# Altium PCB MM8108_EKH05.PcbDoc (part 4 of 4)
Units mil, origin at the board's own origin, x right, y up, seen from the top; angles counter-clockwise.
Board outline 6023.62 x 3425.2 mil, 4 copper layers (Top Layer, Ground Plane, Middle Layer, Bottom Layer), stack 76.15 mil thick; 188 components, 156 nets, 687 pads, 1369 vias.
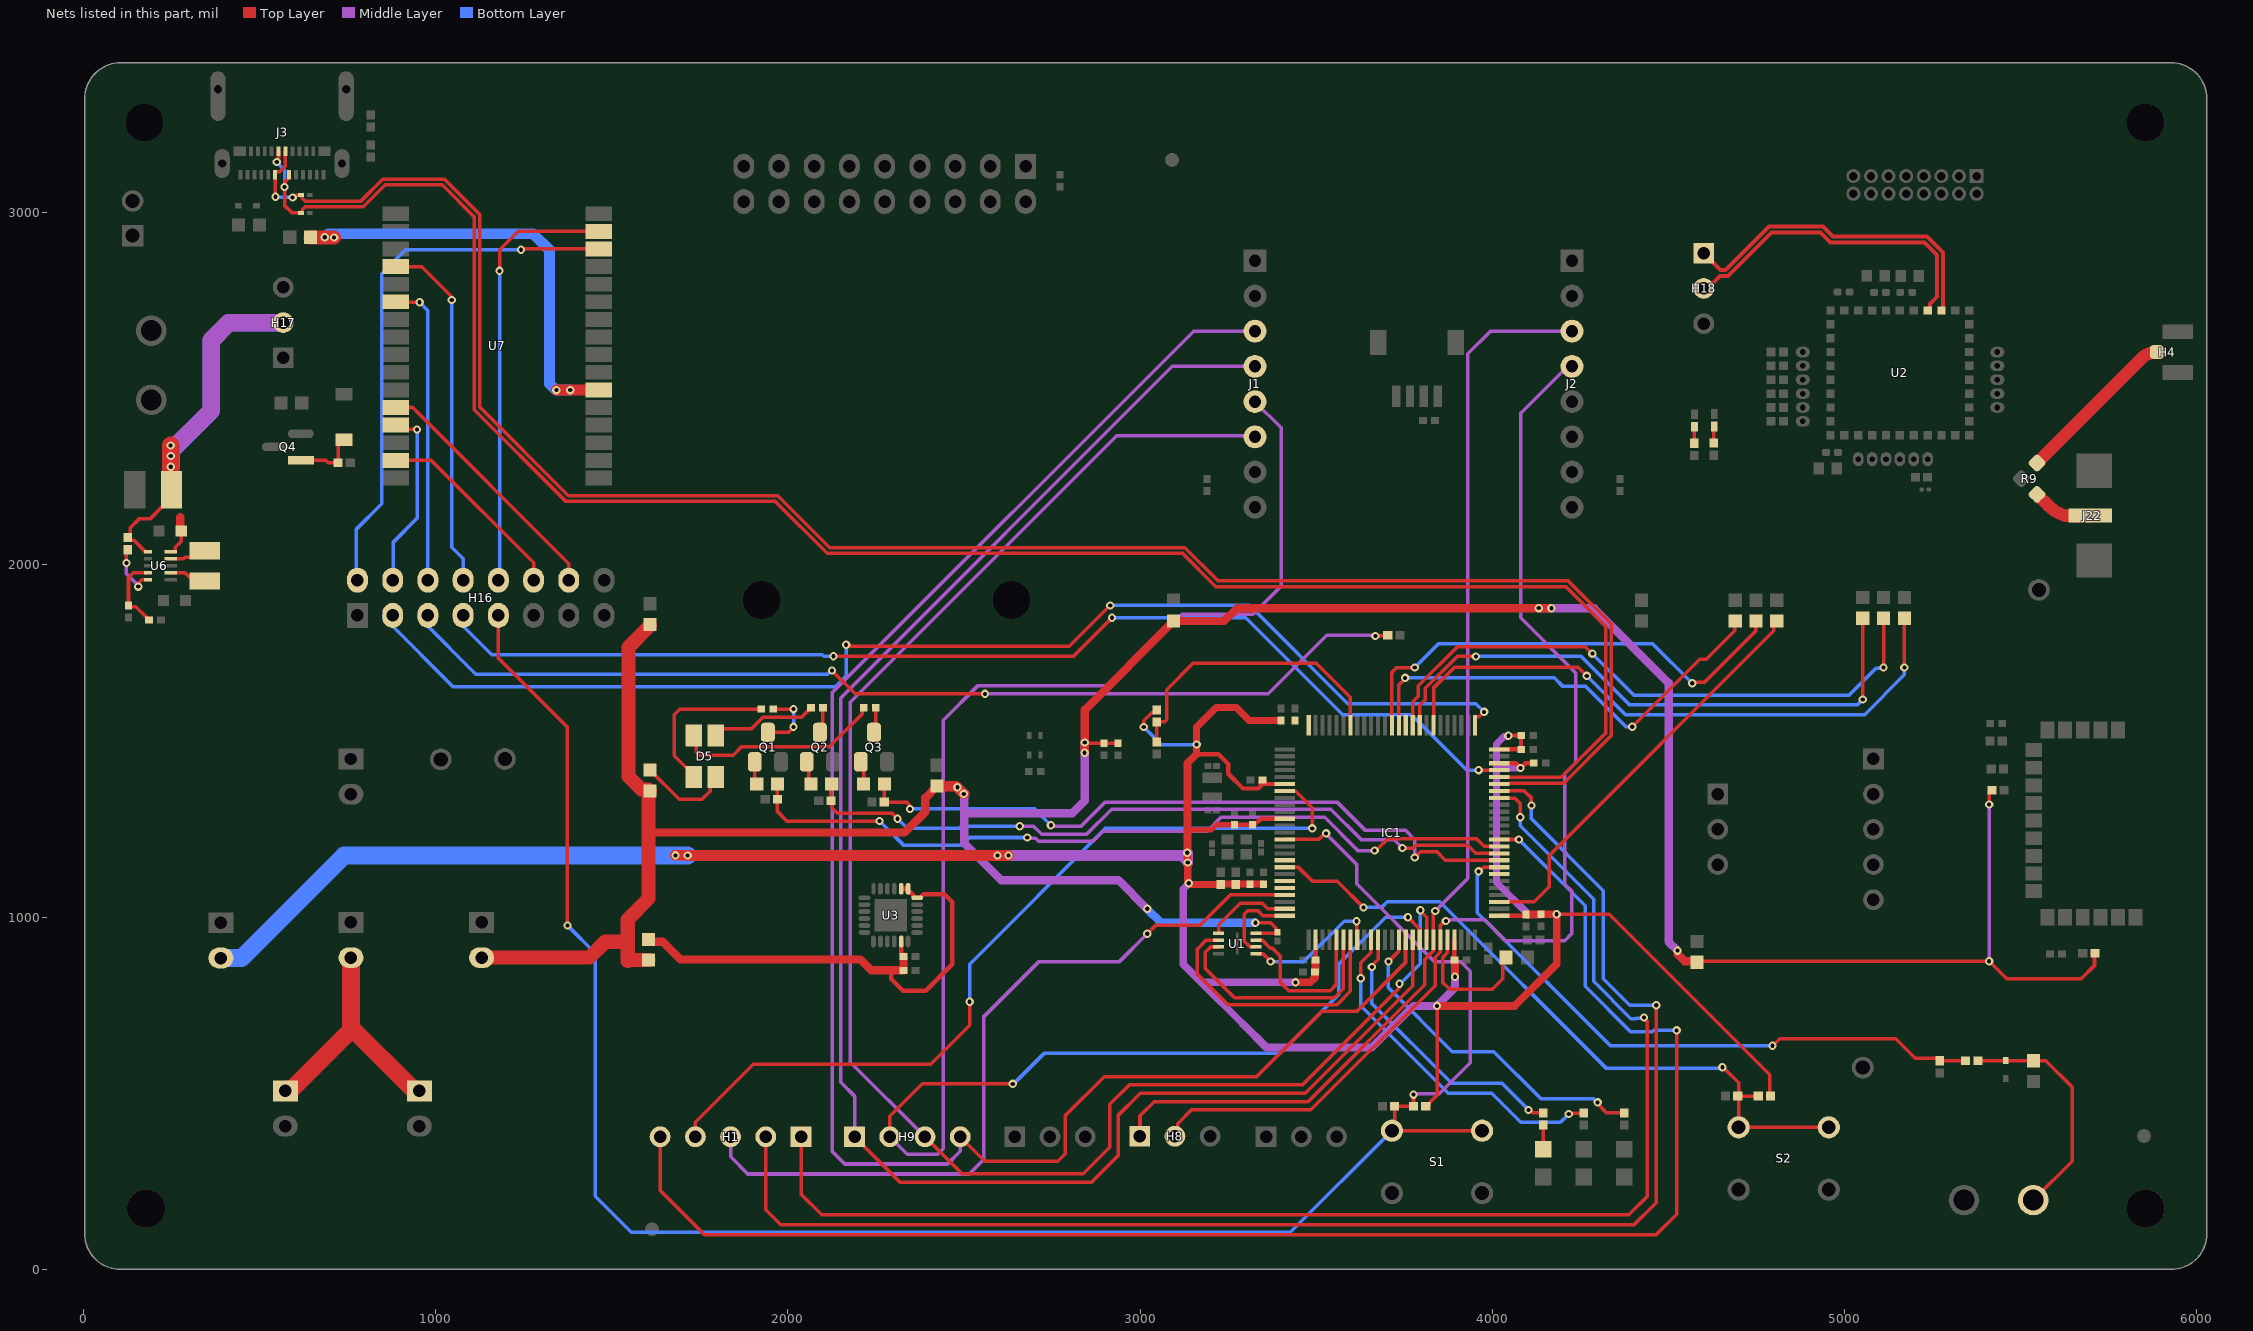
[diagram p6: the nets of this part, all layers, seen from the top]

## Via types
v1: diameter 23.62, hole 11.81, Top Layer to Bottom Layer, tented both sides, 1369 vias

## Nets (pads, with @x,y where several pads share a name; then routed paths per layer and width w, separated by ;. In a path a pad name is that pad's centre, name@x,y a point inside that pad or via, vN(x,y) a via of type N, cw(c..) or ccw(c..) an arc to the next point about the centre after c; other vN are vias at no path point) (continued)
NetD3_A: D3.A R6.2 | length 68.9
  Top Layer w10: D3.A@4143.7,340.94 R6.2@4143.7,409.84
NetD4_K: D4.K H11.2 R51.1 R52.1 | length 665.2
  Top Layer w10: R51.1@5377.95,592.52 D4.K@5456.69,592.52 R52.1@5535.43,592.52 5570.87,592.52 5645.67,517.72 5645.67,307.09 H11.2@5535.43,196.85
NetD5_1: D5.1 R59.1 | length 454.1
  Top Layer w10: D5.1@1732.28,1397.65 1732.28,1405.53 1713.65,1424.15 1711.64,1424.15 1677.17,1458.62 1677.17,1574.8 1692.91,1590.55 R59.1@1923.62,1590.55
NetD5_2: D5.2 R56.2 | length 280.6
  Top Layer w10: R56.2@1621.97,1431.02 R56.2@1608.27,1417.32 1690.94,1334.65 1755.91,1334.65 1778.92,1357.67 1778.92,1381.31 D5.2@1795.27,1397.65
NetD5_3: D5.3 R58.1 | length 303.3
  Top Layer w10: D5.3@1795.27,1515.76 1795.27,1516.81 1813.89,1535.43 1896.96,1535.43 1928.45,1566.93 2037.8,1566.93 R58.1@2065.35,1594.49
NetD5_4: D5.4 R57.1 | length 591.7
  Top Layer w10: D5.4@1732.28,1515.76 1740,1508.04 1740,1470 1750,1460 1844.66,1460 1868.14,1483.48 2117.34,1483.48 2210.71,1576.85 2210.71,1589.91 R57.1@2215.28,1594.49
NetD6_A: D6.A Q4.1 R75.1 | length 184.2
  Top Layer w10: Q4.1@616.82,2297.6 687.4,2297.6 695,2290 R75.1@722.68,2290 722.68,2342.52 735.59,2355.43 D6.A@740,2355.43
NetD7_A: D7.A R17.2 | length 47.7
  Top Layer w10: R17.2@4628.08,2345.89 4628.8,2346.61 4628.8,2392.29 D7.A@4629.53,2393.01
NetD13_A: D13.A R21.2 | length 47.3
  Top Layer w10: R21.2@4572.58,2345.38 4572.75,2345.55 4572.75,2392.32 D13.A@4572.93,2392.5
NetH4_1: H4.1 R9.C | length 467.9
  Top Layer w35.43: R9.C@5545.89,2289.25 5843.39,2586.75 cw(c5885.83,2544.32) H4.1@5885.83,2604.33
NetH16_2: H16.2 U7.30 | length 1548.6
  Top Layer w10: v1(1242.26,2894.52) 1244.59,2896.85 U7.30@1462.76,2896.85
  Bottom Layer w10: H16.2@775,1953.09 775,2101.77 846.46,2173.23 846.46,2826.77 914.21,2894.52 v1(1242.26,2894.52)
NetH16_4: H16.4 U7.13 | length 522.2
  Top Layer w10: U7.13@886.38,2396.85 898.71,2384.52 v1(946.95,2384.52)
  Bottom Layer w10: H16.4@877.76,1956.69 880,1958.94 880,2065 946.95,2131.95 v1(946.95,2384.52)
NetH16_5: H16.5 R3.1 | length 2924.2
  Top Layer w10: v1(2125,1700) 2191.14,1633.86 v1(2559.06,1633.86) ; v1(3667.43,1798.25) 3668.3,1799.13 3701.8,1799.13 R3.1@3702.68,1800
  Middle Layer w10: v1(2559.06,1633.86) 3363.86,1633.86 3530,1800 3665.68,1800 v1(3667.43,1798.25)
  Bottom Layer w10: H16.5@952.76,1856.69 952.76,1850.79 965.26,1838.29 1113.54,1690 2112.33,1690 2122.33,1700 v1(2125,1700)
NetH16_6: H16.6 U7.6 | length 867
  Top Layer w10: U7.6@886.38,2746.85 887.71,2745.51 v1(954.28,2745.51)
  Bottom Layer w10: v1(954.28,2745.51) 977.76,2722.04 H16.6@977.76,1956.69
NetH16_8: H16.8 U7.4 | length 1017.4
  Top Layer w10: U7.4@886.38,2846.85 960.24,2846.85 1047.24,2759.84 v1@1047.24,2748.03
  Bottom Layer w10: v1(1045.28,2751.97) 1045.28,2049.72 1077.76,2017.24 H16.8@1077.76,1956.69
NetH16_10: H16.10 U7.31 | length 1242.1
  Top Layer w10: v1(1181.1,2834.65) 1182.19,2835.73 1182.19,2894.78 1234.25,2946.85 U7.31@1462.76,2946.85
  Bottom Layer w10: H16.10@1177.76,1956.69 1181.1,1960.04 v1(1181.1,2834.65)
NetH16_12: H16.12 U7.15 | length 561
  Top Layer w10: U7.15@886.38,2296.85 986.61,2296.85 1277.76,2005.71 H16.12@1277.76,1956.69
NetH16_14: H16.14 U7.12 | length 721.8
  Top Layer w10: U7.12@886.38,2446.85 934.35,2446.85 1377.76,2003.45 H16.14@1377.76,1956.69
NetIC1_46: IC1.46 L1.2 | length 382.7
  Top Layer w10: IC1.46@3872.05,935.51 3872.05,898.81 3858.27,885.04 3858.27,814.96 3878.23,795 3999.72,795 4029.53,824.8 4029.53,877.36 L1.2@4037.99,885.83
NetJ22_1: J22.1 R9.B | length 172.8
  Top Layer w35.43: R9.B@5545.89,2200.17 5578.07,2167.99 ccw(c5648.78,2238.7) 5609.28,2146.83 5621.46,2141.6 ccw(c5630.83,2163.39) 5629.53,2139.7 5646.84,2138.75 ccw(c5648.78,2174.13) 5648.78,2138.7 J22.1@5697.25,2138.7
NetL3_1: L3.1 U6.9 | length 68.1
  Top Layer w10: U6.9@260.59,2017.05 284.09,2017.05 289.02,2021.97 L3.1@326.61,2021.97
NetL3_2: L3.2 U6.7 | length 84
  Top Layer w10: U6.7@247.87,1977.68 288.23,1977.68 301.02,1964.88 L3.2@326.61,1964.88
NetQ1_D: Q1.D R59.2 | length 187.7
  Top Layer w10: Q1.D@1942.93,1524.37 2000.75,1524.37 2008.94,1532.56 2008.94,1532.81 2015.75,1539.62 v1(2015.75,1540.12) ; R59.2@1958.27,1590.55 v1(2015.75,1590.55)
  Bottom Layer w10: v1(2015.75,1540.12) v1(2015.75,1590.55)
NetQ1_G: Q1.G R62.2 | length 65.4
  Top Layer w10: Q1.G@1905.53,1440.94 1905.53,1383.84 R62.2@1911.42,1377.95
NetQ2_D: Q2.D R58.2 | length 73.7
  Top Layer w10: Q2.D@2090.55,1524.37 2099.21,1533.03 R58.2@2099.21,1594.49
NetQ2_G: Q2.G R63.2 | length 70.5
  Top Layer w10: R63.2@2059.06,1383.86 Q2.G@2059.06,1435.04
  Top Layer w23.62: Q2.G@2053.15,1440.94 Q2.G@2059.06,1435.04 ; R63.2@2059.06,1383.86 R63.2@2064.96,1377.95 ; R63.2@2067.02,1379.83 R63.2@2068.9,1377.95
NetQ3_D: Q3.D R57.2 | length 72.4
  Top Layer w10: Q3.D@2244.11,1524.37 2249.61,1529.87 R57.2@2249.61,1594.49
NetQ3_G: Q3.G R64.2 | length 74.6
  Top Layer w10: Q3.G@2206.71,1440.94 2214.57,1433.09 R64.2@2214.57,1377.95 R64.2@2220.47,1372.05
NetR68_2: R68.2 U6.5 | length 156.7
  Top Layer w10: v1(121.89,2005.24) 121.89,2039.09 R68.2@125.83,2043.03 ; v1(155.35,1938.31) 157.96,1940.91 157.96,1950.65 165.3,1957.99 U6.5@176.1,1957.99
  Middle Layer w10: v1(121.89,2005.24) 121.89,1975.46 154.72,1942.63 v1@154.72,1936.13
NetR71_2: R71.2 R72.1 U6.4 | length 216.3
  Top Layer w10: U6.4@182.91,1977.68 141.57,1977.68 127.79,1963.9 R72.1@127.79,1884.44 130.68,1881.56 148.56,1881.56 179.49,1850.63 180.67,1850.63 186.3,1845 R71.2@186.31,1843.82
NetR73_1: R73.1 U7.22 | length 1325.9
  Top Layer w31: v1(1342.52,2496.06) v1(1381.89,2496.06) 1461.97,2496.06 U7.22@1462.76,2496.85
  Top Layer w40: R73.1@644.53,2930 v1(685,2930) v1@711.44,2930
  Bottom Layer w31: v1@711.44,2940 695,2940 v1(685,2930) 710.71,2930 v1(711.44,2929.28) 722.16,2940 1276.54,2940 1322.83,2893.7 1322.83,2514.22 1340.99,2496.06 v1(1342.52,2496.06) v1(1381.89,2496.06)
PA0: H1.3 IC1.22 | length 2215.6
  Top Layer w10: v1(3019.69,952.76) 3043.31,976.38 3169.29,976.38 3255.91,1062.99 IC1.22@3409.92,1062.99
  Middle Layer w10: H1.3@1837.01,376.69 1837.01,320.09 1886.26,270.84 2514.94,270.84 2555.12,311.02 2555.12,716.54 2712.6,874.02 2940.94,874.02 v1(3019.69,952.76)
PA9: H1.1 IC1.68 | length 3968
  Top Layer w10: H1.1@2037.01,376.69 2037.01,213.61 2095.56,155.06 4387.34,155.06 4440,207.72 4440,702.33 4430,712.33 v1(4430,715) ; IC1.68@4019.21,1338.58 4020.12,1337.68 4063.9,1337.68 4078.74,1322.83 v1@4078.74,1284.32
  Bottom Layer w10: v1(4078.74,1283.46) 4078.74,1259.84 4287.4,1051.18 4287.4,817.6 4392.95,712.05 4408.19,712.05 4408.53,712.39 4427.39,712.39 v1(4430,715)
PA10: H1.2 IC1.69 | length 4217.7
  Top Layer w10: H1.2@1937.01,376.69 1937.01,169.29 1979.38,126.92 4401.92,126.92 4464.54,189.54 4464.54,749.54 v1(4465,750) ; IC1.69@4019.21,1358.27 4090.55,1358.27 4110.63,1338.19 v1(4110.63,1316.83)
  Bottom Layer w10: v1(4110.63,1316.83) 4110.63,1279.13 4314.96,1074.8 4314.96,825.04 4390,750 v1(4465,750)
PC2: IC1.17
PC13: H1.4 IC1.7 | length 2396.4
  Top Layer w10: H1.4@1737.01,376.69 1737.01,418.11 1901.57,582.68 2405.51,582.68 2515.75,692.91 v1(2515.75,759.84) ; IC1.7@3409.92,1358.27 3410.83,1357.36 3441.64,1357.36 3488.19,1310.81 v1(3488.19,1251.97)
  Bottom Layer w10: v1(2515.75,759.84) 2515.75,866.35 2901.37,1251.97 v1(3488.19,1251.97)
PD5: IC1.86
PD10: IC1.57
PD11: C36.1 IC1.58 R51.2 | length 1758.7
  Top Layer w10: v1(3960.63,1129.92) 3963.37,1129.92 3975.18,1141.73 IC1.58@4019.21,1141.73 ; v1(4795,635) 4815,655 5144.62,655 5199.8,599.82 5262.48,599.82 C36.1@5269.69,592.61 ; C36.1@5269.69,592.52 R51.2@5343.31,592.52
  Bottom Layer w10: v1(3960.63,1129.92) 3958.02,1127.31 3958.02,1118.06 3957.21,1117.25 3957.21,1012.79 4335,635 v1(4795,635)
PD15: H1.5 IC1.62 | length 4524.8
  Top Layer w10: H1.5@1637.01,400.68 1637.01,224.1 1762.18,98.92 4465.06,98.92 4522.81,156.67 v1(4522.81,678.54) ; IC1.62@4019.21,1220.47 v1(4074.8,1220.47)
  Bottom Layer w10: v1(4074.8,1220.47) 4262.97,1032.31 4262.97,803.96 4391.93,675 4453.76,675 4457.3,678.54 v1(4522.81,678.54)
PH3-BOOT0: IC1.94 R7.1 R8.1 | length 832.9
  Top Layer w10: R8.1@3047.24,1509.45 R7.1@3047.24,1554.33 ; R7.1@3047.24,1553.54 R7.1@3047.24,1554.33 ; IC1.94@3596.46,1544.8 3596.46,1624.02 3500,1720.47 3149.61,1720.47 3074.8,1645.67 3074.8,1560.19 3068.95,1554.33 R7.1@3047.24,1554.33
SDMMC2_CLK: IC1.87 R31.1 | length 1276.3
  Top Layer w10: IC1.87@3734.25,1544.8 3734.25,1659.18 3751.97,1676.9 v1(3751.97,1679.38) ; v1(4396.65,1540.35) 4527.56,1671.26 4588.58,1732.28 4607.06,1732.28 4687.49,1812.71 4687.49,1839.06 R31.1@4688.98,1840.55
  Bottom Layer w10: v1(3751.97,1679.38) 4175.62,1679.38 4200.12,1654.88 4264.85,1654.88 4379.06,1540.67 4396.33,1540.67 v1(4396.65,1540.35)
SDMMC2_CMD: IC1.88 R32.1 | length 1351.1
  Top Layer w10: IC1.88@3714.57,1544.8 3714.57,1694.88 3728.35,1708.66 v1(3779.53,1708.66) ; v1(4566.93,1664.04) 4569.54,1666.64 4601.97,1666.64 4748.03,1812.71 R32.1@4748.03,1839.06
  Bottom Layer w10: v1(3779.53,1708.66) 3846.46,1775.59 4455.38,1775.59 v1(4566.93,1664.04)
SDMMC2_D0: IC1.53 R33.1 | length 1180.4
  Top Layer w10: IC1.53@4019.21,1043.31 4118.11,1043.31 4161.17,1086.36 4161.17,1174.94 4798.93,1812.71 4798.93,1826.85 4800.21,1828.13 R33.1@4814.35,1828.13
SENSORS_SPI_CLK: H9.1 IC1.41 J1.4 | length 4893.7
  Top Layer w10: H9.1@2188.88,376.69 2317.54,248.03 2862.2,248.03 2937.01,322.83 2937.01,437.01 3000,500 3468.5,500 3773.62,805.12 IC1.41@3773.62,935.51
  Middle Layer w10: H9.1@2188.88,376.69 2188.88,492.22 2149.61,531.5 2149.61,1622.05 3091.14,2563.58 J1.4@3325.59,2563.58
SENSORS_SPI_CS: H9.4 IC1.40 J1.3 | length 5016.4
  Top Layer w10: H9.4@2488.88,376.69 2558.48,307.09 2765.8,307.09 2781.54,322.83 2787.4,328.69 2787.4,437.01 2897.64,547.24 3330.04,547.24 3515.08,732.28 3614.17,732.28 3753.03,871.14 3753.03,934.61 IC1.40@3753.94,935.51
  Middle Layer w10: H9.4@2488.88,376.69 2488.88,335.33 2452.76,299.21 2161.42,299.21 2125.98,334.65 2125.98,1637.8 3151.77,2663.58 J1.3@3325.59,2663.58
SENSORS_SPI_MISO: H9.2 IC1.42 J1.5 | length 4954.8
  Top Layer w10: H9.2@2288.88,376.69 2288.88,434.55 2381.12,526.79 v1(2638.08,526.79) ; v1(3759.7,999.66) 3759.97,999.66 3792.4,967.23 3792.4,936.42 IC1.42@3793.31,935.51
  Middle Layer w10: H9.2@2288.88,376.69 2338.8,326.77 2425.2,326.77 2440.94,342.52 2440.94,1559.06 2539.37,1657.48 2917.32,1657.48 3119.84,1860 3320,1860 3400,1940 3400,2389.17 J1.5@3325.59,2463.58
  Bottom Layer w10: v1@2641.73,527.56 2728.35,614.17 3397.64,614.17 3562.99,779.53 3562.99,866.14 3696.51,999.66 v1(3759.7,999.66)
SENSORS_SPI_MOSI: H9.3 IC1.43 J1.6 | length 4801.9
  Top Layer w10: H9.3@2388.88,376.69 2493.92,271.65 2838.58,271.65 2913.39,346.46 2913.39,468.39 2968.62,523.62 3459.87,523.62 3733.61,797.37 3733.61,808.42 v1(3736.22,811.02) ; v1(3795.28,1019.68) 3795.28,1017.2 3812.99,999.48 IC1.43@3812.99,935.51
  Middle Layer w10: H9.3@2388.88,376.69 2177.17,588.41 2177.17,1610.24 2933.07,2366.14 3323.03,2366.14 J1.6@3325.59,2363.58
  Bottom Layer w10: v1(3736.22,811.02) 3738.41,811.02 3795.28,867.89 v1(3795.28,1019.68)
SENSORS_UART_RX: H8.1 IC1.44 J2.3 | length 3186
  Top Layer w10: H8.1@2998.43,377.95 2999.3,378.83 2999.3,436.31 3039.37,476.38 3476.15,476.38 3807.89,808.12 3807.89,879.92 3831.77,903.79 3831.77,934.61 IC1.44@3832.68,935.51 3831.8,936.39 3831.8,1008.9 3837.51,1014.62 v1(3837.51,1017.31)
  Middle Layer w10: v1(3837.51,1017.31) 3930,1109.79 3930,2599.29 3994.29,2663.58 J2.3@4225.59,2663.58
SENSORS_UART_TX: H8.2 IC1.45 J2.4 | length 3290.3
  Top Layer w10: H8.2@3098.43,377.95 3106.13,385.66 3106.13,413.22 3145.67,452.76 3484.25,452.76 3837,805.5 3837,886.39 3851.46,900.85 3851.46,934.61 IC1.45@3852.36,935.51 3852.36,976.85 3864.51,989 v1(3867.6,989)
  Middle Layer w10: v1(3867.6,989) 3870.2,991.61 3879.75,991.61 3880.27,992.13 3977.87,992.13 4036.93,933.07 4204.72,933.07 4224.41,952.76 4224.41,1074.8 4205.54,1093.68 4205.54,1407.26 4236.22,1437.94 4236.22,1693.3 4080,1849.52 4080,2430.39 4213.19,2563.58 J2.4@4225.59,2563.58 J2.4@4231.69,2563.58
STATUS_LED_B: IC1.36 R6.1 | length 803.6
  Top Layer w10: v1(3657.48,858.27) 3657.48,861.95 3676.1,880.58 3676.1,934.61 IC1.36@3675.2,935.51 ; v1(4102.36,452.76) 4106.05,452.76 4114.32,444.49 R6.1@4143.7,444.49
  Bottom Layer w10: v1(3657.48,858.27) 3657.48,754.79 3884.21,528.06 4027.06,528.06 v1(4102.36,452.76)
STATUS_LED_G: IC1.35 R5.1 | length 980.8
  Top Layer w10: v1(3625.98,826.77) 3625.98,870.08 3654.61,898.7 3654.61,934.61 IC1.35@3655.51,935.51 ; v1(4216.54,440.94) 4218.31,442.72 4257.09,442.72 R5.1@4258.86,444.49
  Bottom Layer w10: v1(3625.98,826.77) 3625.98,748.03 3874.02,500 3997.87,500 4080.55,417.32 4192.91,417.32 v1(4216.54,440.94)
STATUS_LED_R: IC1.39 R4.1 | length 967.7
  Top Layer w10: v1(3704.72,874.02) 3733.35,902.64 3733.35,934.61 IC1.39@3734.25,935.51 ; v1(4298.56,474.16) 4298.56,470.48 4315.31,453.73 4315.31,452.4 4323.23,444.49 R4.1@4374.02,444.49
  Bottom Layer w10: v1(3704.72,874.02) 3704.72,799.21 3885.83,618.11 4003.94,618.11 4137.05,485 4285.9,485 4296.73,474.16 v1(4298.56,474.16)
STM_NRST: C19.1 H16.9 IC1.14 R2.2 S1.1 S1.2 | length 5799
  Top Layer w10: H16.9@1177.76,1865.03 1177.76,1735.63 1374.02,1539.37 v1(1374.02,976.38) ; IC1.14@3409.92,1220.47 3410.83,1221.38 3507.53,1221.38 3523.96,1237.81 v1(3527.65,1237.81) ; v1(3775.59,496.06) 3775.79,495.87 3775.79,462.8 R2.2@3775.98,462.6 C19.1@3722.05,462.6 3722.05,401.18 S1.2@3714.57,393.7 S1.1@3970.47,393.7
  Middle Layer w10: v1(3527.65,1237.81) 3527.65,1236.13 3614.17,1149.61 3614.17,1094.49 3834.65,874.02 3909.45,874.02 3937.01,846.46 3937.01,586.61 3849.06,498.67 3778.2,498.67 v1(3775.59,496.06)
  Bottom Layer w10: v1(1374.02,976.38) 1452.76,897.64 1452.76,207.24 1554.62,105.38 3426.25,105.38 S1.2@3714.57,393.7
STM_QSPI_CLK: IC1.25 U1.6 | length 240.6
  Top Layer w10: U1.6@3328.54,915.35 3312,915.35 3295.28,932.08 3295.28,1007.79 3305.45,1017.97 3334.2,1017.97 3347.98,1004.19 3409.67,1004.19 IC1.25@3409.92,1003.94
STM_QSPI_CS: IC1.24 U1.1 | length 242.8
  Top Layer w10: U1.1@3222.64,954.72 3222.64,978.54 3283.46,1039.37 3346.46,1039.37 3362.2,1023.62 IC1.24@3409.92,1023.62
STM_QSPI_IO0: IC1.33 U1.5 | length 394.5
  Top Layer w10: U1.5@3328.54,895.67 3348.43,895.67 v1(3370.08,874.02) ; v1(3614.17,988.19) 3615.24,987.13 3615.24,936.42 IC1.33@3616.14,935.51
  Bottom Layer w10: v1@3370.94,874.02 3464.57,874.02 3578.74,988.19 v1(3614.17,988.19)
STM_QSPI_IO1: IC1.32 U1.2 | length 775.1
  Top Layer w10: U1.2@3222.64,935.04 3222.56,934.96 3187.22,934.96 3161.42,909.16 3161.42,838.58 3248.03,751.97 3559.06,751.97 3596.46,789.37 IC1.32@3596.46,935.51
STM_QSPI_IO2: IC1.31 U1.3 | length 664.6
  Top Layer w10: 3206.1,915.35 3206.02,915.28 ; U1.3@3222.64,915.35 3222.56,915.28 3206.02,915.28 ; IC1.31@3576.77,935.51 3576.77,797.24 3551.18,771.65 3267.72,771.65 3185.04,854.33 3185.04,900.04 3200.28,915.28 3206.02,915.28
STM_QSPI_IO3: IC1.30 U1.7 | length 465.7
  Top Layer w10: U1.7@3328.54,935.04 3328.62,934.96 3345.94,934.96 3369.07,911.83 3375.57,911.83 3396.88,890.52 3396.88,815.71 3421.26,791.34 3539.37,791.34 3557.09,809.06 IC1.30@3557.09,935.51
STM_SPI2_CLK: IC1.82 R41.2 | length 1729.3
  Top Layer w10: IC1.82@3832.68,1544.8 3832.7,1650.67 3890.94,1708.91 4243.84,1708.91 v1(4267.72,1685.04) ; v1(5169.29,1708.66) R41.2@5169.29,1848.43
  Bottom Layer w10: v1(4267.72,1685.04) 4377.76,1575 5056.31,1575 5169.29,1687.98 v1(5169.29,1708.66)
STM_SPI2_MISO: IC1.84 R43.2 | length 1684.9
  Top Layer w10: IC1.84@3793.31,1544.8 3793.33,1601.38 3809.09,1617.14 3809.09,1649.69 3899.55,1740.16 v1(3952.76,1740.16) ; v1(5051.18,1618.11) R43.2@5051.18,1848.43
  Bottom Layer w10: v1(3952.76,1740.16) 4251.97,1740.16 4389.76,1602.36 5035.43,1602.36 v1(5051.18,1618.11)
STM_SPI2_MOSI: IC1.85 R42.2 | length 1714.5
  Top Layer w10: IC1.85@3773.64,1544.82 3773.64,1611.35 3789.62,1627.32 3789.62,1656.62 3900.71,1767.72 4263.78,1767.72 v1(4283.46,1748.03) ; v1(5110.24,1708.66) R42.2@5110.24,1848.43
  Bottom Layer w10: v1(4283.46,1748.03) 4401.57,1629.92 5012.06,1629.92 5088.2,1706.06 5107.63,1706.06 v1(5110.24,1708.66)
SWD_CLK: H16.3 IC1.76 | length 3541.9
  Top Layer w10: v1(2165,1773.12) 2167.61,1770.52 2176.93,1770.52 2178.88,1768.57 2798.57,1768.57 v1(2915,1885) ; IC1.76@3950.79,1544.8 3950.79,1567.93 3951.69,1568.84 3962.54,1568.84 v1(3976.38,1582.68)
  Bottom Layer w10: H16.3@852.76,1856.69 852.76,1850.79 865.26,1838.29 1049.17,1654.38 2134.38,1654.38 2165,1685 v1(2165,1773.12) ; v1(2915,1885) 3310,1885 3588.7,1606.3 3952.76,1606.3 v1(3976.38,1582.68)
SWD_DIO: H16.7 IC1.72 | length 3234.9
  Top Layer w10: v1(2129.3,1740.7) 2810.7,1740.7 v1(2920,1850) ; v1(3960.63,1417.32) IC1.72@4019.21,1417.32
  Bottom Layer w10: H16.7@1053.94,1849.61 1158.54,1745 2097.49,1745 2101.78,1740.7 v1(2129.3,1740.7) ; v1(2920,1850) 3300,1850 3575.2,1574.8 3770.2,1574.8 3927.68,1417.32 v1(3960.63,1417.32)
TIM4_CH1: IC1.59 R64.1 R67.2 | length 1971.9
  Top Layer w10: R64.1@2273.62,1377.95 2273.23,1377.56 R67.2@2273.23,1326.77 2336.51,1326.77 2343.85,1319.43 2343.85,1309.69 v1(2346.46,1307.09) ; v1(3779.53,1169.29) 3796.48,1186.24 3841.32,1186.24 3866.14,1161.42 IC1.59@4019.21,1161.42
  Middle Layer w10: v1(2746.32,1260.74) 2748.48,1258.59 2832.61,1258.59 2900.79,1326.77 3558.42,1326.77 3637.9,1247.29 3752.4,1247.29 3779.53,1220.16 v1(3779.53,1169.29)
  Bottom Layer w10: v1(2346.46,1307.09) 2699.98,1307.09 v1(2746.32,1260.74)
TIM4_CH2: IC1.60 R63.1 R66.2 | length 2088.7
  Top Layer w10: R63.1@2124.02,1377.95 2122.05,1375.98 R66.2@2122.05,1330.71 2125.64,1327.12 2125.64,1309.36 2139.47,1295.53 2295.02,1295.53 v1(2311.02,1279.53) ; v1(3744.09,1196.19) 3775.19,1196.19 3783,1204 3929.86,1204 3952.76,1181.1 IC1.60@4019.21,1181.1
  Middle Layer w10: v1(2657.88,1258.19) 2696.81,1258.19 2720,1235 2847.59,1235 2918.86,1306.28 3541.01,1306.28 3627.95,1219.34 3721.61,1219.34 3744.09,1196.85 v1(3744.09,1196.19)
  Bottom Layer w10: v1(2311.02,1279.53) 2338.58,1251.97 2485.93,1251.97 2492.16,1258.19 v1(2657.88,1258.19)
TIM4_CH3: IC1.61 R62.1 R65.2 | length 2270
  Top Layer w10: R62.1@1970.47,1377.95 1970.08,1377.56 R65.2@1970.08,1334.65 1970.08,1299.92 1997.28,1272.72 v1(2259.84,1272.72) ; v1(3665.35,1188.98) 3669.04,1188.98 3675.85,1195.79 3676.1,1195.79 3702.31,1222 3955.17,1222 3976.38,1200.79 IC1.61@4019.21,1200.79
  Middle Layer w10: v1(2679.43,1226.13) 2682.03,1223.52 2702.95,1223.52 2711.24,1215.24 2865.88,1215.24 2894.87,1244.23 3189.87,1244.23 3229.11,1283.46 3523.62,1283.46 3618.11,1188.98 v1(3665.35,1188.98)
  Bottom Layer w10: v1(2259.84,1272.72) 2275.84,1256.72 2327.83,1204.72 2494.57,1204.72 2515.98,1226.13 v1(2679.43,1226.13)
USB_D_N: H18.2 U2.27 | length 922.7
  Top Layer w11.13: H18.2@4599.79,2784.94 4611.35,2784.94 4646.11,2819.69 4668.4,2819.69 4792.35,2943.63 4931.59,2943.63 4959.52,2915.71 5226.36,2915.71 5261.71,2880.37 5261.71,2761.22 5241.48,2741 5241.48,2728.69 U2.27@5235.24,2722.44
USB_D_P: H18.1 U2.28 | length 946.9
  Top Layer w11.13: H18.1@4599.79,2884.94 4647.26,2837.47 4661.96,2837.47 4785.25,2960.76 4938.69,2960.76 4966.61,2932.84 5233.46,2932.84 5278.83,2887.47 5278.83,2726.67 U2.28@5274.61,2722.44
USBC_N: D12.K IC1.70 J3.A7 J3.B7 | length 5507.1
  Top Layer w10: J3.A7@544.09,3107.48 544.09,3045.91 v1(545,3045) ; J3.A7@544.49,3116.14 557.11,3116.14 571.21,3130.24 573.23,3132.26 573.23,3174.02 J3.B7@573.62,3174.41 ; v1(593.75,3042.96) 597.37,3042.96 603.63,3049.21 617.01,3049.21 D12.K@617.8,3050 ; D12.K@620.16,3050 620.94,3049.21 620.94,3041.36 629.33,3032.98 787.98,3032.98 850,3095 1025,3095 1125.47,2994.53 1125.47,2447.26 1376.39,2196.34 1970.88,2196.34 2118.09,2049.12 3126.81,2049.12 3221.45,1954.49 4215.51,1954.49 4337.13,1832.87 4337.13,1515.57 4202.18,1380.61 4049.13,1380.61 4047.25,1378.74 4020,1378.74 IC1.70@4019.21,1377.95
  Bottom Layer w10: v1(545,3045) 546.02,3043.98 592.73,3043.98 v1(593.75,3042.96)
USBC_P: D11.K IC1.71 J3.A6 J3.B6 | length 5495.6
  Top Layer w10: J3.A6@583.46,3107.48 583.07,3107.09 583.07,3098.82 573.38,3089.13 573.38,3075.52 v1(570.82,3072.96) 570.82,3020.17 591.77,2999.22 D11.K@617.8,2999.22 ; D11.K@620.95,3000.01 620.95,3007.86 629.83,3016.74 794.7,3016.74 856.73,3078.76 1018.27,3078.76 1109.24,2987.8 1109.24,2440.53 1369.66,2180.1 1964.15,2180.1 2111.37,2032.89 3120.09,2032.89 3214.72,1938.26 4208.78,1938.26 4320.89,1826.14 4320.89,1522.29 4195.45,1396.85 4020,1396.85 IC1.71@4019.21,1397.64
  Top Layer w10.24: v1(548.41,3143.81) 548.41,3147.43 553.54,3152.56 553.54,3174.02 J3.B6@553.94,3174.41
  Bottom Layer w10: v1(548.41,3143.81) 548.41,3142.97 570.82,3120.56 v1(570.82,3072.96)
USER_BUTTON: C20.1 IC1.18 R1.2 S2.1 S2.2 | length 1995.1
  Top Layer w10: IC1.18@3409.92,1141.73 3410.52,1141.14 3449.42,1141.14 3488.88,1101.67 3559.75,1101.67 v1(3633.86,1027.56) ; v1(4652.66,573.92) 4654.43,573.92 4698.82,529.53 C20.1@4698.82,492.13 ; R1.2@4754.33,492.13 C20.1@4698.82,492.13 ; S2.1@4954.72,403.54 S2.2@4698.82,403.54 C20.1@4698.82,492.13
  Bottom Layer w10: v1(3633.86,1027.56) 3685.04,1027.56 3701.13,1043.65 3850.05,1043.65 4322.09,571.61 4650.35,571.61 v1(4652.66,573.92)
VDD_HALOW: H3.1 H19.1 H21.2 | length 724.8
  Top Layer w50: H19.1@572.83,506.69 577.36,511.22 590.73,511.22 763.12,683.62 935.52,511.22 948.88,511.22 H3.1@953.41,506.69 ; 759.39,687.35 H21.2@759.39,885
VDD_MCU: C1.2 C2.2 C3.2 C4.2 C5.2 C6.2 C7.2 C8.2 C9.1 C10.2 C11.2 C14.2 C15.2 C16.2 C17.2 C18.2 C21.2 H24.2 IC1.6 IC1.11 IC1.20 IC1.21 IC1.27 IC1.47 IC1.51 IC1.73 IC1.75 IC1.100 R1.1 R2.1 R7.2 | length 9370.8
  Top Layer w10: v1(3010,1540) 3010,1557.05 3033.14,1580.2 3040.04,1580.2 3047.24,1587.4 R7.2@3047.24,1588.19 ; C18.2@3348.82,1094.49 C18.2@3350.39,1092.91 ; R2.1@3812.62,464.59 3842.52,494.49 v1(3842.52,748.03) ; v1(4045,1515) v1@4045.37,1515.37 ; C10.2@4080.73,1515.37 C10.2@4081.1,1515.75 ; v1(4182.14,1008.07) 4331.93,1008.07 4787.4,552.6 R1.1@4787.4,492.13
  Top Layer w12: 3159.45,1462.6 3222.4,1462.6 3250,1435 3250,1406.98 3291.98,1365 3335,1365 3342,1372 3342,1379 ; C3.2@3267.72,1262.2 C2.2@3318.9,1262.2 ; C2.2@3322.05,1259.06 3342.52,1279.53 IC1.11@3409.92,1279.53 ; IC1.6@3409.92,1377.95 3360.05,1377.95 ; C4.2@3497.31,874.02 3498.03,874.73 IC1.27@3498.03,935.51 ; C9.1@3891.73,878.35 IC1.47@3891.73,935.51 ; IC1.51@4019.21,1003.94 4019.31,1004.03 C6.2@4097.03,1004.03 ; IC1.73@4019.21,1437.01 4066.1,1437.01 v1(4079.67,1423.44) 4093.24,1437.01 C15.2@4116.86,1437.01 ; IC1.75@4019.21,1476.38 4081.1,1476.38 C10.2@4081.1,1515.75 ; v1@4045.37,1515.37 C10.2@4080.73,1515.37 ; 3342,1379 3342,1386 3346,1390 C1.2@3347,1390 3348,1390 3360.05,1377.95 ; 3342,1379 3343.05,1377.95 3360.05,1377.95
  Top Layer w15: 3133.86,1248.03 3202.18,1248.03 3216.35,1262.2 C3.2@3267.72,1262.2
  Top Layer w20: v1(3137.8,1096.12) 3138.78,1096.12 3141.98,1092.91 C17.2@3228.35,1092.91 ; 3159.45,1462.6 3159.45,1539.27 3214.81,1594.63 3272.78,1594.63 3309.41,1558 C14.2@3400,1558 ; C17.2@3232.28,1094.49 C18.2@3348.82,1094.49
  Top Layer w22: v1@3134.47,1155.53 3134.69,1155.75 3133.86,1156.58 3133.86,1248.03 3133.86,1437.01 3159.45,1462.6 ; v1(3135,1155) 3135,1099.35 3137.8,1096.56 v1(3137.8,1096.12) ; v1(3440.94,814.96) 3482.14,814.96 3496.02,828.85 C5.2@3496.02,844.11 3497.31,845.4 C4.2@3497.31,874.02 ; R2.1@3810.63,462.6 3811.42,462.6 3812.62,463.8 R2.1@3812.62,464.59 ; v1@3842.96,748.03 4063.03,748.03 4182.14,867.14 v1(4182.14,1008.07) ; C9.1@3892.45,877.95 3892.45,868.78 3893.7,867.53 v1(3893.7,830.71) ; C6.2@4095.37,1007.6 C7.2@4136.5,1007.6 ; C7.2@4137.08,1008.19 4181.39,1008.19 v1@4181.61,1007.97
  Top Layer w30: v1(1680.47,1175.49) 1714.51,1175.49 v1(1715,1175) v1(2595,1175) 2625.52,1175 v1(2625.78,1175.26)
  Middle Layer w20: v1(3137.8,1096.12) 3137.8,1095.14 3122.05,1079.39 3122.05,866.14 3173.23,814.96 3291.34,696.85 ; v1(4045,1515) 4043.16,1513.16 4033.08,1513.16 4011.81,1491.89 4011.81,1423.44 ; v1(4079.67,1423.44) 4011.81,1423.44 ; v1(4182.14,1008.07) 4101.63,1008.07 4011.81,1097.89 4011.81,1423.44
  Middle Layer w22: 3173.23,814.96 3409.45,814.96 ; 3291.34,696.85 3358.27,629.92 3657.48,629.92 3775.59,748.03 v1(3842.52,748.03) 3893.7,799.21 v1(3893.7,830.71) ; v1@3440.51,814.96 3409.45,814.96 ; v1(3440.94,814.96) 3409.45,814.96
  Middle Layer w30: v1(2595,1175) 3117.43,1175 v1@3135,1157.43 ; v1(3133.59,1182.79) 3135,1181.38 v1@3135,1157.43 ; v1(3135,1155) v1@3135,1157.43
  Bottom Layer w10: v1(3010,1540) 3060,1490 v1(3160,1490)
  Bottom Layer w50: H24.2@390.05,884 448.71,884 739.71,1175 1680.47,1175 v1(1715,1175)
VDD_SENSORS: C24.2 H25.2 R47.1 R48.1 R50.1 R53.1 R54.1 R55.1 R56.1 R61.1 R82.1 R85.1 U1.8 | length 8913
  Top Layer w10: v1@2845.2,1493.38 R85.1@2897.64,1493.38 R82.1@2937.01,1493.38 ; v1(3326.77,984.25) 3370.08,984.25 3386.5,967.83 3386.5,958.07 3389.76,954.8 3328.62,954.8 U1.8@3328.54,954.72 ; R47.1@4583.66,875 v1(5410,875) 5460,825 5671.46,825 5709.05,862.6 R50.1@5709.05,897.24 ; v1(5410,1320) 5410,1352.8 5417.2,1360 R48.1@5417.68,1360
  Top Layer w23.62: R56.1@1604.33,1362.2 R56.1@1608.27,1358.27 ; 1608.27,1240.16 2330.71,1240.16 2389.76,1299.21 2389.76,1338.58 R54.1@2423.23,1372.05 ; v1(2842.23,1466.59) 2842.52,1466.88 v1(2842.52,1496.06) 2842.52,1588.58 R61.1@3094.49,1840.55 3238.19,1840.55 3274.45,1876.81 4131.08,1876.81 v1(4131.46,1877.19) 4166.67,1877.19 v1(4167.08,1876.77) ; v1(4525,905) 4525,895 4545,875 4577.76,875 R47.1@4580.71,872.05 R47.1@4583.66,875 ; R50.1@5709.05,897.24 5709.45,897.64 R50.1@5710.24,897.64
  Top Layer w30: R54.1@2423.23,1372.05 v1@2477.95,1372.05 ; v1(2480.74,1368.61) 2480.74,1368.42 v1(2499.09,1350.07)
  Top Layer w40: H25.2@1130.05,885 1202.86,885 1436.18,885 1481.3,930.12 1545,930.12 ; R53.1@1604.33,877.95 1547.95,877.95 1545,875 1545,930.12 ; R56.1@1604.33,1362.2 1584.14,1362.2 1546.84,1399.51 1546.84,1766.09 R55.1@1608.27,1827.52 ; R56.1@1608.27,1358.27 1604.33,1354.33 1604.33,1240.16 1604.33,1053.15 1545,993.82 1545,930.12
  Middle Layer w10: v1(5410,875) v1(5410,1320)
  Middle Layer w23.62: v1@2500,1350 2500,1299.21 ; v1(2842.23,1466.59) 2842.23,1495.77 v1(2842.52,1496.06) ; v1@2842.52,1466.59 2842.52,1330.71 2807.09,1295.28 2503.94,1295.28 2500,1299.21 ; v1(3019.69,1023.62) 2938.31,1105 2605,1105 2500,1210 2500,1299.21 ; v1(4131.46,1877.19) v1@4166.67,1877.19 ; v1(4167.08,1876.77) 4288.58,1876.77 4500,1665.35 4500,930 v1(4525,905)
  Middle Layer w30: v1(2480.74,1368.61) 2499.35,1350 v1@2500,1350
  Bottom Layer w23.62: v1(3019.69,1023.62) 3059.06,984.25 v1(3326.77,984.25)
VDD_SENSORS_ACC: C37.2 C38.2 R53.2 U3.5 U3.12 U3.13 U3.14 | length 1434.1
  Top Layer w12: 2180,880.95 2180.95,880 ; 2293,849 2293,824 2326,791 2391,791 2466.23,866.23 2466.23,1043.23 2444.47,1065 2384.37,1065 2376.79,1057.42 2376.79,1055.82 2375.97,1055 U3.12@2366.61,1055 2357.25,1055 2356.42,1055.82 2356.42,1062.28 2348.3,1070.41 2341.84,1070.41 2341.02,1071.23 U3.13@2341.02,1080.59 U3.14@2321.33,1080.59 ; C37.2@2321.33,896.32 U3.5@2321.33,930.98
  Top Layer w23.62: R53.2@1604.33,937.01 1611.22,930.12 1644.88,930.12 1695,880 2180.95,880 2206,880 2237,849 2293,849 C38.2@2328,849 C37.2@2328,888
VIN: C42.2 C49.1 H17.2 R68.1 U6.1 U6.10 | length 1762.9
  Top Layer w10: R68.1@125.83,2077.68 125.83,2076.89 133.03,2069.69 143.23,2069.69 176.18,2036.73 U6.1@182.91,2036.73 ; R68.1@126.22,2077.28 132.9,2083.97 132.9,2105.67 158.91,2131.68 190.07,2131.68 223.04,2164.64 C49.1@224.34,2164.64 ; U6.10@247.87,2036.73 260.51,2036.73 260.59,2036.81 260.59,2049.72 277.4,2066.54 C42.2@277.4,2095.79 ; C49.1@249.85,2190.16 C49.1@249.85,2212.79
  Top Layer w23.62: C49.1@241.17,2259.26 C49.1@247.92,2252.5 ; 275.05,2135.46 275.05,2098.14 C42.2@277.4,2095.79
  Top Layer w50: v1@247.28,2308.97 247.92,2308.33 v1(247.92,2278.53) 247.92,2252.5 C49.1@247.92,2212.79 ; v1(247.28,2338.82) 247.52,2338.59 v1(247.52,2308.97)
  Middle Layer w50: v1(247.92,2278.53) 247.92,2323.61 362.19,2437.88 362.19,2637.19 412.87,2687.87 H17.2@566.93,2687.87
  Bottom Layer w50: v1(247.92,2278.53) 247.92,2323.21 362.66,2437.95 362.66,2637.66 412.87,2687.87 H17.2@566.93,2687.87
pads on no net: FID1.1 FID2.1 FID3.1 H5.7 H5.15 IC2.1 IC2.2 IC2.3 IC2.4 IC2.6 IC2.9 IC2.10 IC2.14 IC2.18 IC2.20 J3.A2 J3.A3 J3.A8 J3.A10 J3.A11 J3.B2 J3.B3 J3.B8 J3.B10 J3.B11 M1.1 M2.1 M3.1 M4.1 MH1.1 MH2.1 U3.1 U3.2 U3.15 U3.17 U3.18 U3.19 U3.20 U3.21 U3.22 U3.23 U3.24 U7.1 U7.2 U7.3 U7.7 U7.9 U7.10 U7.11 U7.14 U7.16 U7.17 U7.18 U7.19 U7.20 U7.21 U7.23 U7.25 U7.28 U7.32

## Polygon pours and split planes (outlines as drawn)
GND on Top Layer "Top_GND" (solid, remove dead copper, pour order 19): 23.04,3202.63 23.04,3338.85 cw(c123.04,3338.85) 123.04,3438.85 5946.66,3438.85 cw(c5946.66,3338.85) 6046.66,3338.85 6046.66,113.65 cw(c5946.66,113.65) 5946.66,13.65 123.04,13.65 cw(c123.04,113.65) 23.04,113.65 23.04,289.24
BAT_POS on Top Layer "NONET_L-01_P-001" (solid, pour order 9): 135,2545 255,2545 290,2510 557.29,2510 585,2482.29 585,2436.64 573.4,2425.04 573.4,2321.51 461.07,2321.15 432.69,2394.74 287.4,2395.5 125,2396.34 125,2535
BAT_VIN on Top Layer "BAT_VIN_L01_P011" (solid, pour order 11): 517.24,2631.02 517.24,2552.76 530,2540 555,2540 600,2495 600,2400 580,2380 580,2365 585,2360 659.36,2360 765,2465.64 765,2523.5 658.5,2630 600,2630
VDD_MCU on Top Layer "VDD_MCU_L01_P018" (solid, pour order 18): 3350.5,1103.9 3377.17,1103.9 3381.09,1107.83 3381.32,1107.61 3436.64,1107.61 3438.66,1105.59 3438.66,1078.54 3436.98,1076.86 3378.18,1076.86 3372.79,1082.25 3350.28,1082.25
VDD_MCU on Top Layer "NONET_L-01_P-001" (solid, pour order 17): 3390,1570 3478.76,1570 3484.07,1564.69 3483.91,1564.52 3483.91,1519.91 3417.07,1519.91 3390,1546.98
GND on Bottom Layer "GND_L04_P005" (solid, remove dead copper, pour order 5): 3.94,3188.98 3.94,3325.2 cw(c103.94,3325.2) 103.94,3425.2 5927.56,3425.2 cw(c5927.56,3325.2) 6027.56,3325.2 6027.56,100 cw(c5927.56,100) 5927.56,0 103.94,0 cw(c103.94,100) 3.94,100 3.94,275.59
GND on Middle Layer "GND_L03_P007" (solid, remove dead copper, pour order 7): 3.94,3188.98 3.94,3325.2 cw(c103.94,3325.2) 103.94,3425.2 5927.56,3425.2 cw(c5927.56,3325.2) 6027.56,3325.2 6027.56,100 cw(c5927.56,100) 5927.56,0 103.94,0 cw(c103.94,100) 3.94,100 3.94,275.59
GND on Ground Plane (split plane): 5950.87,3402.03 5965.41,3396.01 5978.49,3387.26 5989.62,3376.13 5998.37,3363.05 6004.39,3348.5 6007.46,3333.07 6007.46,3325.2 6007.46,2300.22 5827.89,2300.21 5826.71,2302.43 5824.21,2305.48 5818.67,2311.01 5815.62,2313.51 5814.01,2314.38 5812.15,2315.37 5804.91,2318.37 5801.14,2319.51 5797.22,2319.9 5789.39,2319.9 5785.47,2319.51 5782.04,2318.47 5781.7,2318.37 5774.47,2315.37 5770.99,2313.52 5767.95,2311.02 5762.41,2305.48 5759.91,2302.43 5759.05,2300.82 5758.05,2298.96 5755.06,2291.72 5754.76,2290.75 5753.91,2287.95 5753.73,2286.14 5753.53,2284.03 5753.53,2280.12 5753.53,2166.24 5624.69,2166.24 5624.69,2166.23 5617.26,2171.14 5608.16,2177.5 5567.93,2137.28 5573.11,2133.54 5590.34,2122.98 5597.32,2120.09 5598.85,2119.19 5610.55,2114.26 5617.26,2111.75 5624.98,2110.73 5624.98,2110.79 5753.53,2111.23 5753.53,1999.41 5753.53,1995.49 5753.91,1991.57 5755.05,1987.8 5758.05,1980.57 5759.91,1977.09 5762.41,1974.05 5767.95,1968.51 5770.99,1966.01 5774.47,1964.15 5781.7,1961.16 5785.47,1960.01 5789.39,1959.63 5797.22,1959.63 5801.14,1960.01 5804.91,1961.16 5812.15,1964.15 5815.62,1966.01 5818.67,1968.51 5824.21,1974.05 5826.7,1977.09 5827.89,1979.31 6007.46,1979.31 6007.46,1838.58 5791.34,1838.58 5791.34,681.1 6007.46,681.1 6007.46,100 6007.46,92.13 6004.39,76.69 5998.37,62.15 5989.62,49.06 5978.49,37.94 5965.41,29.19 5950.87,23.17 5935.43,20.1 103.94,20.1 96.07,20.1 80.63,23.17 66.09,29.19 53,37.93 41.87,49.06 33.13,62.15 27.1,76.69 24.03,92.13 24.03,100 24.03,275.59 24.03,3188.98 24.03,3325.2 24.03,3333.07 27.1,3348.5 33.13,3363.04 41.87,3376.13 53,3387.26 66.09,3396.01 80.63,3402.03 96.07,3405.1 103.94,3405.1 5935.43,3405.1

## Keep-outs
Keep-Out Layer:
  circle w7.87: c5854.33,3251.97 r110.24
  circle w7.87: c5854.33,173.23 r110.24
  circle w7.87: c177.17,173.23 r110.24
  circle w7.87: c173.23,3255.91 r110.24

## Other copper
Top Layer:
  rectangle net BAT_VIN: 543.87,2544.22 561.32,2559.1
  rectangle net BAT_VIN: 592.11,2607.86 619.82,2616.84
Ground Plane (plane layer: these items are gaps in the copper):
  lines w40: 2621.98,1334.68 2779.45,1334.68 2779.45,1334.65 2783.37,1334.65 2790.6,1337.64 2796.14,1343.18 2799.14,1350.42 2799.14,1354.33 2799.14,1551.21 2799.43,1555.42 2796.75,1563.42 2791.21,1569.79 2783.66,1573.55 2779.45,1573.84 ; 2621.98,1334.68 2621.98,1334.69 ; 2621.98,1334.69 2618.06,1334.69 2610.82,1337.69 2605.29,1343.23 2602.29,1350.46 2602.29,1354.38 2602.29,1558.22 2602.29,1561.33 2604.66,1567.07 2609.06,1571.46 2614.8,1573.84 2617.9,1573.84 2621.97,1573.84 2656.62,1573.84 ; 2656.62,1545.33 2659.09,1545.41 2663.5,1547.6 2666.63,1551.41 2667.89,1556.17 2667.49,1558.6 ; 2656.62,1545.33 2656.62,1545.33 ; 2656.62,1545.33 2653.7,1545.03 2648.29,1542.77 2644.16,1538.62 2641.94,1533.2 2641.66,1530.27 2641.66,1440.82 2641.83,1393.72 2642.2,1389.88 2645.14,1382.79 2650.57,1377.35 2657.67,1374.41 2661.51,1374.04 2740.06,1374 2743.9,1374.37 2751,1377.31 2756.43,1382.75 2759.37,1389.84 2759.75,1393.68 2759.77,1393.68 2759.77,1530.27 ; 2656.62,1573.84 2656.62,1573.84 ; 2656.62,1573.84 2659.26,1573.49 2663.83,1570.75 2666.92,1566.42 2668.02,1561.21 2667.49,1558.6 ; 2667.49,1558.6 2667.49,1558.6 ; 2744.8,1545.33 2747.73,1545.03 2753.13,1542.77 2757.26,1538.62 2759.49,1533.2 2759.77,1530.27 ; 2744.8,1545.33 2744.8,1545.33 ; 2744.8,1545.33 2742.58,1545.4 2738.53,1547.21 2735.45,1550.4 2733.79,1554.51 2733.79,1556.73 2733.79,1566.58 2733.79,1568.02 2734.9,1570.69 2736.94,1572.73 2739.61,1573.84 2741.05,1573.84 2779.45,1573.84 ; 2759.77,1530.27 2759.77,1530.27 ; 2779.45,1573.84 2779.45,1573.84 ; 3.94,90.15 3.94,100 3.94,275.59 3.94,3188.98 3.94,3325.2 3.94,3335.05 7.78,3354.37 15.32,3372.56 26.26,3388.94 40.19,3402.87 56.57,3413.82 74.77,3421.35 94.09,3425.2 103.94,3425.2 5937.41,3425.2 5956.73,3421.35 5974.93,3413.82 5991.31,3402.87 6005.23,3388.94 6016.18,3372.56 6023.72,3354.37 6027.56,3335.05 6027.56,3325.2 6027.56,2280.12 5812.99,2280.12 5812.99,2284.03 5810,2291.27 5804.46,2296.8 5797.22,2299.8 5789.39,2299.8 5782.16,2296.81 5776.62,2291.27 5773.62,2284.03 5773.62,2280.12 5773.62,1999.41 5773.62,1995.49 5776.62,1988.26 5782.16,1982.72 5789.39,1979.72 5797.22,1979.72 5804.46,1982.72 5810,1988.26 5812.99,1995.49 5812.99,1999.41 6027.56,1999.41 6027.56,100 6027.56,90.15 6023.72,70.83 6016.18,52.63 6005.23,36.25 5991.31,22.32 5974.93,11.38 5956.73,3.84 5937.41,0 103.94,0 94.09,0 74.77,3.84 56.57,11.38 40.19,22.32 26.26,36.25 15.32,52.63 7.78,70.83 3.94,90.15

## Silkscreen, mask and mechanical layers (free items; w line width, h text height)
Top Overlay:
  circle w10: c5437.44,616.06 r1.1
  circle w10: c780.55,2490.93 r1.49
  circle w10: c334.22,2078.9 r1.49
  rectangle: 3706.43,2648.41 3863.99,2675
  lines w7.09: 547.2,2895 547.2,2965 685,2965 685,2895 547.2,2895 ; 1555.12,838.58 1653.54,838.58 1653.54,976.38 1555.12,976.38 1555.12,838.58 ; 1559.06,1318.9 1657.48,1318.9 1657.48,1456.69 1559.06,1456.69 1559.06,1318.9 ; 1559.06,1791.34 1657.48,1791.34 1657.48,1937.01 1559.06,1937.01 1559.06,1791.34 ; 2374.02,1332.68 2472.44,1332.68 2472.44,1470.47 2374.02,1470.47 2374.02,1332.68 ; 3045.28,1801.18 3143.7,1801.18 3143.7,1938.98 3045.28,1938.98 3045.28,1801.18 ; 4374.02,1801.18 4472.44,1801.18 4472.44,1938.98 4374.02,1938.98 4374.02,1801.18 ; 4531.5,832.68 4629.92,832.68 4629.92,970.47 4531.5,970.47 4531.5,832.68 ; 4649.61,1802.17 4848.43,1802.17 4848.43,1989.17 4649.61,1989.17 4649.61,1802.17 ; 5013.78,1801.18 5212.6,1801.18 5212.6,1988.19 5013.78,1988.19 5013.78,1801.18
  lines w7.87: 947.55,1170.54 948.62,1169.47
  lines w10: 439.73,1035.07 575.2,1170.54 947.55,1170.54 ; 622.77,557.81 760.91,695.95 ; 760.63,1169.78 760.63,1297.66 ; 760.71,1039.71 760.71,1171.35 ; 761.98,701.58 761.98,831.8 ; 762.53,698.1 903.54,557.09 ; 948.62,1169.47 1082.01,1035.77 ; 1822.83,2657.48 2728.35,2657.48 ; 1925.2,2401.57 1925.2,2909.45 ; 1990.63,950.37 2017.26,977.27 ; 2016.99,976.31 2016.99,1044.89 ; 2017.32,976.3 2082.01,976.3 ; 2027.56,2401.57 2027.56,2909.45 ; 2125.98,2401.57 2125.98,2909.45 ; 2228.35,2401.57 2228.35,2909.45 ; 2322.83,2401.57 2322.83,2909.45 ; 2425.2,2401.57 2425.2,2909.45 ; 2527.56,2401.57 2527.56,2909.45 ; 2625.98,2401.57 2625.98,2909.45 ; 5988.07,2415.61 5988.19,2501.97 ; 5988.19,856.3 5988.19,169.29 5988.19,114.17 cw(c5913.39,114.17) 5913.39,39.37 5842.52,39.37 5151.57,39.37 ; 5988.19,1732.28 5988.19,1861.22 ; 5988.19,2724.41 5988.19,3303.15 5988.19,3311.02 ccw(c5913.39,3311.02) 5913.39,3385.83 4501.97,3385.83 ; 43.31,1771.65 43.31,3279.53 43.31,3312.02 cw(c117.11,3312.02) 117.11,3385.83 196.85,3385.83 1529.53,3385.83 ; 43.31,1771.65 1529.53,1771.65 ; 43.31,1771.65 43.31,157.48 43.31,118.11 ccw(c122.05,118.11) 122.05,39.37 1529.53,39.37 ; 1529.53,39.37 4501.97,39.37 ; 1529.53,39.37 1529.53,807.09 ; 1529.53,807.09 3015.75,807.09 ; 1529.53,807.09 1529.53,1299.21 ; 1529.53,807.09 4501.97,807.09 ; 1529.53,1299.21 2342.52,1299.21 ; 1529.53,1299.21 1529.53,1771.65 ; 1529.53,1299.21 3015.75,1299.21 ; 1529.53,1771.65 2342.52,1771.65 ; 1529.53,1771.65 3015.75,1771.65 ; 1529.53,1771.65 1529.53,3385.83 ; 1529.53,3385.83 3015.75,3385.83 ; 2342.52,1299.21 2342.52,1771.65 ; 2342.52,1299.21 3015.75,1299.21 ; 2342.52,1299.21 2342.52,1771.65 ; 2342.52,1771.65 3015.75,1771.65 ; 3015.75,807.09 3015.75,1299.21 ; 3015.75,807.09 4501.97,807.09 ; 3015.75,807.09 3015.75,1771.65 ; 3015.75,1299.21 3015.75,1771.65 ; 3015.75,1771.65 4501.97,1771.65 ; 3015.75,1771.65 3015.75,3385.83 ; 3015.75,1771.65 3015.75,3385.83 ; 3015.75,1771.65 4501.97,1771.65 ; 3015.75,3385.83 4501.97,3385.83 ; 4501.97,39.37 4501.97,807.09 ; 4501.97,39.37 5151.57,39.37 ; 4501.97,39.37 4501.97,807.09 ; 4501.97,807.09 5988.19,807.09 5988.19,1771.65 4501.97,1771.65 ; 4501.97,807.09 4501.97,1771.65 ; 4501.97,807.09 4501.97,1771.65 ; 4501.97,807.09 5151.57,807.09 5151.57,39.37 ; 4501.97,1771.65 4501.97,3385.83 ; 1822.83,2401.57 2728.35,2401.57 2728.35,2909.45 1822.83,2909.45 1822.83,2401.57
  text "Wi-Fi HaLow" at 4539.37,3230.06 h118.11
  text "CAMERA" at 1568.9,3228.35 h118.11
  text "MIKROBUS / QWIIC" at 3055.12,3225.34 h118.11
  text "-" at 382.2,3035.09 h200 r90
  text "DEBUG HEADER" at 4765,3008.32 h50
  text "USB" at 4545.73,2948.46 h50
  text "+" at 299.62,2864.67 h160
  text "D+" at 4664.35,2855.55 h50
  text "D-" at 4664.07,2753.5 h50
  text "USB" at 618.11,2732.17 h80
  text "3V3" at 2707.17,2685.04 h62.99 r90
  text "RST" at 1907.96,2679.44 h62.99 r90
  text "D1" at 2007.18,2679.44 h62.99 r90
  text "D3" at 2107.1,2679.44 h62.99 r90
  text "D5" at 2206.84,2679.44 h62.99 r90
  text "D7" at 2305.93,2679.44 h62.99 r90
  text "PIXCLK" at 2406.37,2679.44 h62.99 r90
  text "VSYNC" at 2506.81,2679.44 h62.99 r90
  text "SCL" at 2607.25,2679.44 h62.99 r90
  text "QWIIC" at 3649.67,2671.37 h70
  text "-" at 470.85,2654.98 h200 r90
  text "GND" at 4663.24,2655.09 h50
  text "VIN" at 618.11,2632.17 h80
  text "BAT" at 618.11,2535.96 h80
  text "USER LEDS" at 4536.18,2465.44 h50
  text "PWDN" at 1906.52,2433.46 h62.99 r90
  text "D0" at 2006.04,2433.47 h62.99 r90
  text "D2" at 2105.43,2433.46 h62.99 r90
  text "D4" at 2204.68,2433.47 h62.99 r90
  text "D6" at 2304.72,2433.47 h62.99 r90
  text "XCLK" at 2405.34,2433.46 h62.99 r90
  text "HYSNC" at 2505.95,2433.46 h62.99 r90
  text "SDA" at 2606.56,2433.47 h62.99 r90
  text "GND" at 2707.17,2433.47 h62.99 r90
  text "+" at 387.5,2389.27 h160
  text "TX" at 1303.31,2020.75 h50 r90
  text "RX" at 1405.67,2020.75 h50 r90
  text "T_VCC" at 806.85,2016.46 h50 r90
  text "SWCLK" at 906.85,2016.46 h50 r90
  text "SWO" at 1001.89,2016.46 h50 r90
  text "SWDIO" at 1098.59,2016.46 h50 r90
  text "NRST" at 1206.85,2016.46 h50 r90
  text "GND" at 1509.17,2016.46 h50 r90
  text "SDIO" at 4681.1,1927.41 h50
  text "SPI" at 5072.83,1927.41 h50
  text "GND" at 5410.85,1751.23 h50
  text "HOST MCU" at 3047.24,1618.24 h118.11
  text "CURRENT MEASUREMENT" at 77.76,1615.49 h118.11
  text "TEMP." at 2377.95,1615.59 h118.11
  text "BLUETOOTH" at 4551.18,1615.59 h118.11
  text "RGB LED" at 1559.06,1614.17 h118.11
  text "BLE_SCK" at 5157.48,1437.98 h50
  text "BLE_SWCLK" at 4712.6,1335.62 h50
  text "BLE_MOSI" at 5161.42,1335.62 h50
  text "3V3" at 703.88,1314.13 h100 r90
  text "0x44" at 2757.58,1303.15 h90
  text "GND" at 1071.55,1295.46 h50
  text "GND" at 889.67,1294.46 h50
  text "BLE_MISO" at 5161.42,1235.62 h50
  text "BLE_SWDIO" at 4712.6,1233.26 h50
  text "ACCELEROMETER" at 1568.9,1151.71 h118.11
  text "BLE_CS" at 5161.42,1135.62 h50
  text "GND" at 4712.6,1130.51 h50
  text "+Y" at 1987,1077 h53.15
  text "BLE_IRQ" at 5161.42,1035.62 h50
  text "+X" at 2115.79,960.66 h53.15
  text "+Z" at 1920,892 h53.15
  text "MCU" at 325.78,835.49 h100 r90
  text "0x19" at 2736.99,824.82 h90
  text "HALOW" at 692.86,766.42 h100 r90
  text "SENSORS" at 1293.65,724.88 h100 r90
  text "STM32 DEBUG" at 1563.98,657.48 h118.11
  text "BUTTON" at 4543.31,657.48 h118.11
  text "CURR. SENSE" at 5194.14,657.48 h118.11
  text "4-20mA" at 5618.11,518.39 h100
  text "SENS. I2C" at 2605.1,480.35 h100
  text "SENS. UART" at 2961.01,480.35 h100
  text "DBG UART" at 3305.5,480.35 h100
  text "STM RESET" at 3675.88,480.33 h100
  text "STATUS LEDS" at 4029.04,480.33 h100
  text "SPARE / GPIO" at 1566.88,478.35 h100
  text "SENS. SPI" at 2201.56,478.39 h100
  text "-" at 5355,474.14 h200 r180
  text "GND" at 4932.68,405.56 h50
  text "+" at 5584.78,395 h160 r90
  text "VDDIO" at 1119.35,311.48 h100 r90
  text "VBAT" at 509.32,306.62 h100 r90
  text "CS" at 2503.35,241.47 h50 r90
  text "PA0" at 1853.74,218.09 h50 r90
  text "PA9" at 2048.23,217.63 h50 r90
  text "SCL" at 2652.95,212.73 h50 r90
  text "SCK" at 2208.07,206.54 h50 r90
  text "SDA" at 2756.3,206.63 h50 r90
  text "GND" at 2859.65,204.28 h50 r90
  text "GND" at 3215.95,204.28 h50 r90
  text "GND" at 3566.34,204.28 h50 r90
  text "PC13" at 1751.38,192.91 h50 r90
  text "PA10" at 1948.23,192.91 h50 r90
  text "PD15" at 1656.89,192.04 h50 r90
  text "MOSI" at 2404.92,191.07 h50 r90
  text "MISO" at 2306.5,189.96 h50 r90
  text "DBG_TX" at 3470.19,121.35 h50 r90
  text "DBG_RX" at 3361.23,116.41 h50 r90
  text "SENS_TX" at 3119.79,97.23 h50 r90
  text "SENS_RX" at 3010.84,92.29 h50 r90
  text "MM8108-EKH05 V2" at 332.2,13.53 h118.11
Bottom Overlay:
  lines w10: 1901.57,503.87 3141.73,503.87 ; 1901.57,505 1901.57,799.21 3141.73,799.21
  text "-" at 275,3015 h200 r90
  text "+" at 195,2885.22 h160
  text "-" at 345,2645 h200 r90
  text "+" at 265,2415.22 h160
  text "6V MAX" at 29.08,2410.47 h80 r270
  text "MM8108-EKH05 V2" at 3897.64,846.46 h200
  text "SERIAL:" at 3899.53,499.57 h150
Top Assembly:
  lines w10: 6026.57,1998.35 5812.01,1998.35 5812.01,1994.43 5809.01,1987.2 5803.47,1981.66 5796.24,1978.66 5788.41,1978.66 5781.17,1981.66 5775.63,1987.2 5772.64,1994.43 5772.64,1998.35 5772.64,2277.09 5772.64,2281 5775.64,2288.24 5781.17,2293.77 5788.41,2296.77 5796.24,2296.77 5803.47,2293.77 5809.01,2288.24 5812.01,2281 6026.57,2281 ; 6027.56,1996.65 6027.56,118.11 6027.56,100.72 cw(c5926.84,100.72) 5926.84,0 5909.45,0 2056.3,0 240.16,0 98.03,0 cw(c98.03,94.09) 3.94,94.09 3.94,236.22 3.94,3188.98 ; 6027.56,2281 6027.56,3299.21 6027.56,3324.48 ccw(c5926.84,3324.48) 5926.84,3425.2 5870.08,3425.2 1576.38,3425.2 240.16,3425.2 104.66,3425.2 ccw(c104.66,3324.48) 3.94,3324.48 3.94,3188.98 ; 3.94,3188.98 3.94,3188.98
Fab Notes:
  lines w3.94: -58.84,-1054.17 -58.84,-602.42 1478.22,-602.42 1478.22,-1054.62 -58.39,-1054.62 ; 474.62,-1053.22 474.62,-602.42 ; 474.62,-964.17 1479.54,-964.17 ; 474.62,-874.07 1479.54,-874.07 ; 474.62,-783.52 1479.54,-783.52 ; 474.62,-692.97 1479.54,-692.97 ; 1182.3,-1055.61 1182.3,-965.06
  text "NOTES: UNLESS OTHERWISE SPECIFIED0" at -3357.21,2832.86 h60
  text "1. SPECIFICATIONS/TOLERANCES:" at -3357.21,2762.86 h60
  text "A. FABRICATE PER IPC-6012, CLASS 2, USING PROVIDED DATA FILES XXXXXXXX.ZIP" at -3357.21,2692.86 h60
  text "B. ALL SPECIFICATIONS USED SHALL BE PER THEIR LATEST REVISIONS." at -3357.21,2622.86 h60
  text "C. THE DIMENSIONS OF CIRCUIT FEATURES IN THE PROVIDED DATA MAY BE ADJUSTED" at -3357.21,2552.86 h60
  text "ONLY TO COMPENSATE FOR PROCESS TOLERANCES; ADDING, REMOVING OR RELOCATING" at -3357.21,2482.86 h60
  text "CIRCUIT FEATURES IS NOT ALLOWED" at -3357.21,2412.86 h60
  text "D. REMOVE ALL BURRS AND BREAK SHARP EDGES, .381 [.015] MAX RADIUS." at -3357.21,2342.86 h60
  text "E. PARENTHETICAL INFORMATION IS FOR REFERENCE ONLY." at -3357.21,2272.86 h60
  text "F. REPAIR OF PCB DEFECTS IS NOT PERMITTED." at -3357.21,2202.86 h60
  text "2. DIELECTRIC MATERIAL:" at -3357.25,2062.86 h60
  text "A. DIELECTRIC MATERIAL SHALL BE PER IPC-4101/99, /124, /126 OR /129 (RoHS COMPLIANT EPOXY-GLASS)" at -3357.21,1992.86 h60
  text "B. MINIMUM DIELECTRIC THICKNESS SHALL BE .051 [.002] FOR REFERENCED STACK-UP" at -3357.21,1922.86 h60
  text "DIMENSIONS OF.076 [.003] OR GREATER; IPC-6012 REQUIREMENTS SHALL OTHERWISE" at -3357.21,1852.86 h60
  text "APPLY. SINGLE-PLY CONSTRUCTION IS ALLOWED." at -3357.21,1782.86 h60
  text "C. SEE LAYER STACK-UP FOR REQUIRED COPPER WEIGHTS AND THE FINISHED PCB" at -3357.21,1712.86 h60
  text "THICKNESS. IF SPECIFIED, 1/3 OZ. STARTING FOIL MAY BE ACHIEVED BY 1/2 OZ. FOIL REDUCTION." at -3357.21,1642.86 h60
  text "D. FINISHED PCB THICKNESS SHALL BE MEASURED OVER LANDS AND/OR" at -3357.21,1572.86 h60
  text "CONDUCTORS NOT COVERED BY SOLDER MASK. IF SPECIFIED, 1/3 OZ. STARTING FOIL" at -3357.21,1502.86 h60
  text "MAY BE ACHIEVED BY 1/2 OZ. FOIL REDUCTION." at -3357.21,1432.86 h60
  text "3. DRILLING:" at -3357.21,1292.86 h60
  text "A. VIA DIAMETERS SHALL BE VERIFIED BEFORE PLATING; ALL OTHER HOLE" at -3357.21,1222.86 h60
  text "DIAMETERS ARE FINISHED DIMENSIONS." at -3357.21,1152.86 h60
  text "B. LAYER-TO-LAYER MISREGISTRATION SHALL BE .127 [.005] MAXIMUM." at -3357.21,1082.86 h60
  text "4. SOLDER MASK:" at -3357.21,942.86 h60
  text "A. APPLY LPI SOLDER MASK OVER BARE COPPER USING PROVIDED DATA." at -3357.21,872.86 h60
  text "B. SOLDER MASK SHALL BE PER IPC-SM-840, CLASS T, COLOR PURPLE." at -3357.21,802.86 h60
  text "C. THE DIMENSIONS OF SOLDER MASK-DEFINED PADS ON PLANES AND/OR WIDE" at -3357.21,732.86 h60
  text "CONDUCTORS SHALL NOT BE MODIFIED." at -3357.21,662.86 h60
  text "5. SILKSCREEN/MARKING:" at -3357.21,522.86 h60
  text "A. SILKSCREEN PCB PER PROVIDED DATA USING PERMANENT, NON-CONDUCTIVE" at -3357.21,452.86 h60
  text "INK, COLOR WHITE." at -3357.21,382.86 h60
  text "B. SUPPLIER ID AND TRACEABILITY INFORMATION SHALL NOT / BE APPLIED ON ANY PART OF THE PCB" at -3356.19,209.11 h60
  text "C. INK SHALL NOT BE APPLIED TO ANY SOLDERABLE SURFACE." at -3357.21,133.49 h60
  text "USING PROVIDED DATA." at -3357.21,63.49 h60
  text "6. ELECTRICAL TEST:" at -3357.21,-76.51 h60
  text "A. DESIGN VERIFICATION SHALL BE DONE PRIOR TO PCB FABRICATION USING" at -3357.21,-146.51 h60
  text "GERBER DATA AND AN IPC-D-356 NETLIST." at -3357.21,-216.51 h60
  text "B. ALL PCBS SHALL BE 100% ELECTRICALLY TESTED FOR OPENS AND SHORTS" at -3357.21,-286.51 h60
  text "C. APPLY TEST STAMP IN NON-LEGEND AREA ON SECONDARY SIDE OF PCB." at -3357.21,-356.51 h60
  text "7. FINAL FINISH:" at -3357.21,-491.51 h60
  text "A. FINAL FINISH SHALL BE ELECTROLESS NICKEL/IMMERSION GOLD (ENIG) PER IPC-4552." at -3357.21,-565.54 h60
  text "Project:" at 492.34,-665.41 h60
  text "MM8108-EKH05" at 753.17,-670.33 h80
  text "8. IMPEDANCE:" at -3360.68,-673.63 h60
  text "A. IMPEDANCE TOLERANCE SHALL BE +/- 10%." at -3360.68,-743.63 h60
  text "Company:" at 492.34,-755.96 h60
  text "Morse Micro" at 753.22,-760.88 h80
  text "B. SEE LAYER STACK-UP FOR IMPEDANCE REQUIREMENTS." at -3360.68,-813.63 h60
  text "Drawn By:" at 492.34,-846.51 h60
  text "B. Attride" at 753.17,-853.4 h80
  text "9. IF PANELIZATION SPECIFICATIONS ARE PROVIDED, THE PCBS SHALL BE DELIVERED IN PANEL" at -3347.21,-936.51 h60
  text "FORM. HOWEVER, THESE SPECIFICATIONS MAY BE REPLACED BY SUPPLIER PREFERRED" at -3347.21,-1006.51 h60
  text "Date:" at 492.34,-1027.06 h60
  text "Rev:" at 1210.84,-1031 h60
  text ".Print_Date" at 753.17,-1037.89 h80
  text ".PCBRev" at 1338.8,-1038.76 h80
  text "(SPECIFICATIONS AS APPROVED)." at -3347.21,-1076.51 h60
Board:
  drawing of 166 lines, arcs and shapes, not listed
